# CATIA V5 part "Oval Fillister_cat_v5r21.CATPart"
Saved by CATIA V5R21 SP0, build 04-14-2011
Part number: Oval Fillister
Bounding box of the stored display mesh (mm): x -5 to 5, y -5 to 5, z -7 to 4
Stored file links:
  D:\CATIA V5R21 E-RESOURCES\CATIA-V5R21\catia-v5r21-Tut\c13-catia-v5r21-tut\c13-catia-v5r21-tut02\Bench Vice\Oval Fillister_cat_v5r21.CATPart
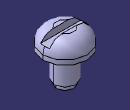
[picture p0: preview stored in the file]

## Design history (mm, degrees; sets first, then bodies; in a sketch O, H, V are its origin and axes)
Body1 (main body)
  Sketch1 on xy-plane, origin (0, 0, 0), H (1, 0, 0), V (0, 1, 0)
    circle A1 centre (0, 0) radius 5
    radius A1 = 5
  Pad1: profile Sketch1, direction (0, 0, 1), length 4
  Sketch2 on face of Pad1, origin (0, 0, 0), H (1, 0, 0), V (0, -1, 0)
    circle A1 centre (0, 0) radius 2.5
    radius A1 = 2.5
  Pad2: profile Sketch2, direction (0, 0, -1), length 6
  Sketch3 on face of Pad2, origin (0, 0, -6), H (1, 0, 0), V (0, -1, 0)
    circle A1 centre (0, 0) radius 2
    radius A1 = 2
  Pad3: profile Sketch3, direction (0, 0, -1), length 1
  Fillet1: radius 3, on 1 edge
  Sketch4 on yz-plane, origin (0, 0, 0), H (0, 1, 0), V (0, 0, 1)
    line L1 (-1, 4.5549) -> (1, 4.5549)
    line L2 (1, 4.5549) -> (1, 2.5)
    line L3 (1, 2.5) -> (-1, 2.5)
    line L4 (-1, 2.5) -> (-1, 4.5549)
    distance H L3 = 2.5
    distance L2 V = 1
    length L1 = 2
    horizontal: L1 H, L3 H
    vertical: L2 V, L4 V
  Pocket1: profile Sketch4, direction (-1, 0, 0), length 8, mirrored extent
